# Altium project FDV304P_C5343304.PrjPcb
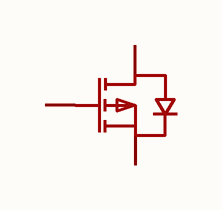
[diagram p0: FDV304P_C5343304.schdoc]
1 sheet, 1 parts. Net scope: global (net labels, ports and power ports of the same name join across sheets).

## Sheet FDV304P_C5343304.schdoc
size 127 x 101 mm

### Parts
Q?  fdv304p  [SOT-23-3_L2.9-W1.3-P1.90-LS2.4-BR]  (value not drawn)

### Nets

Not connected (* = marked no-connect by the designer): Q? 1(G) 2(S) 3(D)

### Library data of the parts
Q? = fdv304p: 数量:1个P沟道;漏源电压(Vdss):30V;连续漏极电流(Id):1.5A;导通电阻(RDS(on)):900mΩ@10V;耗散功率(Pd):1.11W;阈值电压(Vgs(th)):900mV;; Manufacturer: MSKSEMI(美森科); Symbol: FDV304P_C5343304; AddInBom: yes; ModelId: c62791f0466c4ae2a892c056b845b0ca; ModelName: SOT-23-3P_L2.9-W1.3-H1.0-LS2.4-P0.95; ModelTransform: 98.425,114.173,0,180,0,0,0.0005,-0.0005,0; Number: 1个P沟道; Drain to Source Voltage: 30V; Current - Continuous Drain(Id): 1.5A; Pd - Power Dissipation: 1.11W; Gate Threshold Voltage (Vgs(th)): 900mV; Gate Charge(Qg): 12.5nC@10V; Input Capacitance(Ciss): 810pF; Reverse Transfer Capacitance (Crss@Vds): 50pF; Type: P沟道; Output Capacitance(Coss): 85pF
